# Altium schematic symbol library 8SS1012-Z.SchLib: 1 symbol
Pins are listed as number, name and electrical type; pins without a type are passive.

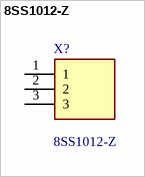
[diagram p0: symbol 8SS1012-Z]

## 8SS1012-Z
designator X?
NIDEC COPAL ELECTRONICS - 8SS1012-Z - SLIDE SWITCH, SPDT, 6A, 125VAC, TH; Geometry.Height: 14.75mm
footprint 8SS1012Z
pins: 1, 2, 3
